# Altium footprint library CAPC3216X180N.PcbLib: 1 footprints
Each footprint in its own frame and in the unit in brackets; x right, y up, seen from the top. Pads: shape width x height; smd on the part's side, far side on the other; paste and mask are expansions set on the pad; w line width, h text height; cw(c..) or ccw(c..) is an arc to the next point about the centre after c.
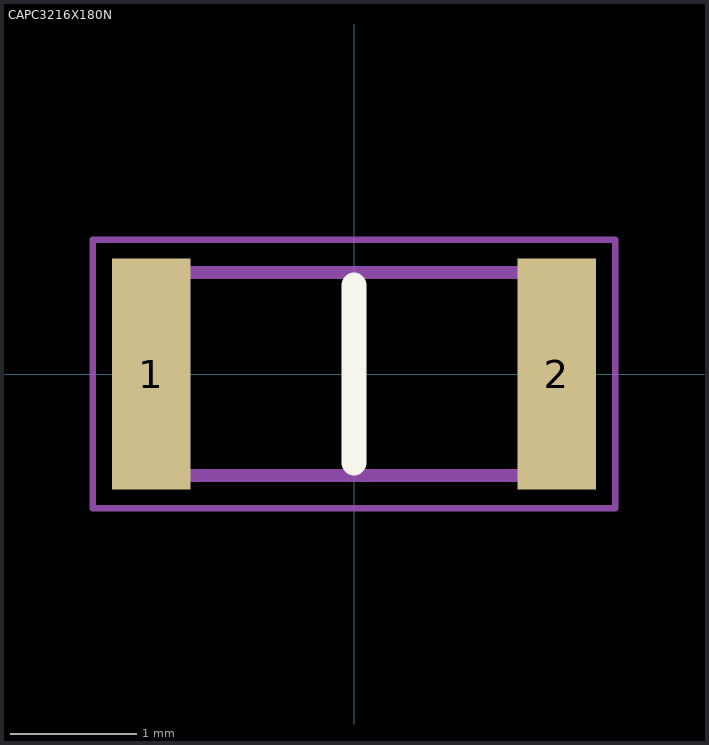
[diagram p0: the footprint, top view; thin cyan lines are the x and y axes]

## CAPC3216X180N [mm]
pads (2):
  rect 0.62x1.82 smd: 1(-1.6,0) 2(1.6,0)
Top Overlay:
  lines w0.2: 0,-0.7 0,0.7
Mechanical 15:
  lines w0.1: -1.6,-0.8 1.6,-0.8 1.6,0.8 -1.6,0.8 -1.6,-0.8
Mechanical 20:
  lines w0.05: -2.06,-1.06 2.06,-1.06 2.06,1.06 -2.06,1.06 -2.06,-1.06
3D body "C3216X7R1H106K160AE.stp": height 5.8, standoff -4.65, extent -10,-3.376 10,3.376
